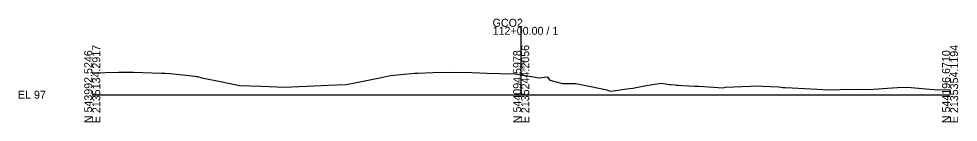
# Model space of a CAD drawing. Extents: x -14327 to 8886, y -10 to 39048.
# Drawn here: x 4974.3 to 5302.8, y 3990.3 to 4026.7 of the extents above; entities that cross this region are included whole.
import ezdxf

# ---------------------------------------------------------------- set-up
doc = ezdxf.new("R2010")
doc.units = 0
for name, color, linetype in [('RD_GPK_XS_Cell', 7, 'Continuous'), ('RD_XS_ExGround', 7, 'Continuous'), ('RD_XS_TX_Elev_EX', 7, 'Continuous')]:
    doc.layers.add(name, color=color, linetype=linetype)

msp = doc.modelspace()

# ---------------------------------------------------------------- linework, layer by layer
at = {"layer": 'RD_GPK_XS_Cell'}
for p, q in [((5150, 4000), (5150, 4023.85)), ((5000, 4000), (5150, 4000)), ((5150, 4000), (5300, 4000))]:
    msp.add_line(p, q, dxfattribs=at)
at = {"layer": 'RD_XS_ExGround'}
for p, q in [((5000, 4007.64), (5009.14, 4007.88)), ((5009.14, 4007.88), (5011.68, 4007.95)), ((5011.68, 4007.95), (5014.45, 4007.86)), ((5014.45, 4007.86), (5024.21, 4007.56)), ((5024.21, 4007.56), (5025.44, 4007.51)), ((5025.44, 4007.51), (5027.25, 4007.42)), ((5027.25, 4007.42), (5035.96, 4006.47)), ((5035.96, 4006.47), (5036.4, 4006.42)), ((5036.4, 4006.42), (5036.78, 4006.34)), ((5036.78, 4006.34), (5038.37, 4005.97)), ((5038.37, 4005.97), (5045.47, 4004.56)), ((5092.41, 4004.33), (5101.16, 4006.08)), ((5101.16, 4006.08), (5103.1, 4006.51)), ((5103.1, 4006.51), (5104.41, 4006.77)), ((5104.41, 4006.77), (5106.69, 4007)), ((5106.69, 4007), (5111.54, 4007.45)), ((5111.54, 4007.45), (5112.64, 4007.53)), ((5112.64, 4007.53), (5113.85, 4007.6)), ((5113.85, 4007.6), (5119.11, 4007.74)), ((5119.11, 4007.74), (5126.11, 4007.93)), ((5126.11, 4007.93), (5132.71, 4007.76)), ((5132.71, 4007.76), (5138.05, 4007.61)), ((5138.05, 4007.61), (5142.64, 4007.46)), ((5142.64, 4007.46), (5147.95, 4007.31)), ((5147.95, 4007.31), (5150, 4006.95)), ((5150, 4006.95), (5152.2, 4006.57)), ((5152.2, 4006.57), (5156.19, 4005.9)), ((5156.19, 4005.9), (5158.16, 4006.12)), ((5158.16, 4006.12), (5159.1, 4006.28)), ((5159.1, 4006.28), (5159.57, 4005.65)), ((5159.57, 4005.65), (5160, 4005.06)), ((5160, 4005.06), (5161.28, 4004.71)), ((5045.47, 4004.56), (5051.51, 4003.2)), ((5051.51, 4003.2), (5059.2, 4003.01)), ((5059.2, 4003.01), (5067.18, 4002.66)), ((5067.18, 4002.66), (5082.57, 4003.33)), ((5082.57, 4003.33), (5088.79, 4003.59)), ((5088.79, 4003.59), (5092.41, 4004.33)), ((5161.28, 4004.71), (5164.46, 4003.91)), ((5164.46, 4003.91), (5167.41, 4003.91)), ((5167.41, 4003.91), (5169.1, 4003.91)), ((5169.1, 4003.91), (5174.37, 4002.83)), ((5174.37, 4002.83), (5179.99, 4001.66)), ((5179.99, 4001.66), (5180.83, 4001.37)), ((5181.22, 4001.25), (5183.15, 4001.53)), ((5183.15, 4001.53), (5186.07, 4001.97)), ((5186.07, 4001.97), (5189.1, 4002.26)), ((5189.1, 4002.26), (5193.08, 4003.08)), ((5193.08, 4003.08), (5199.01, 4004.09)), ((5199.01, 4004.09), (5200.47, 4003.85)), ((5200.47, 4003.85), (5201.92, 4003.55)), ((5201.92, 4003.55), (5202.31, 4003.56)), ((5202.31, 4003.56), (5203.85, 4003.44)), ((5203.85, 4003.44), (5204.3, 4003.38)), ((5204.3, 4003.38), (5205.03, 4003.35)), ((5205.03, 4003.35), (5206.56, 4003.25)), ((5206.56, 4003.25), (5210.71, 4003.05)), ((5210.71, 4003.05), (5212.13, 4002.97)), ((5212.13, 4002.97), (5220.63, 4002.45)), ((5220.63, 4002.45), (5221.51, 4002.68)), ((5221.51, 4002.68), (5230.24, 4003.02)), ((5230.24, 4003.02), (5231.52, 4003.1)), ((5231.52, 4003.1), (5240.07, 4002.72)), ((5240.07, 4002.72), (5241.52, 4002.54)), ((5241.52, 4002.54), (5242.31, 4002.54)), ((5242.31, 4002.54), (5244.75, 4002.44)), ((5244.75, 4002.44), (5257.72, 4001.74)), ((5257.72, 4001.74), (5261.54, 4001.82)), ((5261.54, 4001.82), (5267.95, 4001.89)), ((5267.95, 4001.89), (5271.54, 4001.8)), ((5271.54, 4001.8), (5278.16, 4002.33)), ((5278.16, 4002.33), (5281.55, 4002.53)), ((5281.55, 4002.53), (5285.09, 4002.64)), ((5285.09, 4002.64), (5291.56, 4002.03)), ((5291.56, 4002.03), (5295.7, 4001.66)), ((5295.7, 4001.66), (5300, 4001.78)), ((5180.83, 4001.37), (5181.22, 4001.25))]:
    msp.add_line(p, q, dxfattribs=at)

# ---------------------------------------------------------------- texts
at = {"layer": 'RD_GPK_XS_Cell'}
for s, p in [('GCO2', (5140, 4023.85)), ('112+00.00 / 1', (5140, 4021.05)), ('EL 97', (4974, 3998.6))]:
    msp.add_text(s, height=2.8, dxfattribs=at).set_placement(p)
for s, p in [('N 543992.5246', (5000, 3990)), ('E 2135134.2917', (5002.8, 3990)), ('N 544094.5978', (5150, 3990)), ('E 2135244.2056', (5152.8, 3990)), ('N 544196.6710', (5300, 3990)), ('E 2135354.1194', (5302.8, 3990))]:
    msp.add_text(s, height=2.8, rotation=90, dxfattribs=at).set_placement(p)
at = {"layer": 'RD_XS_TX_Elev_EX'}
msp.add_text('103.95', height=1, rotation=90, dxfattribs=at).set_placement((5151.25, 4007.95))

doc.saveas('drawing.dxf')
